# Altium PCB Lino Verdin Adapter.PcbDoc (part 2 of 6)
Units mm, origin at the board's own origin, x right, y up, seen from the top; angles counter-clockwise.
Board outline 69.6 x 35 mm, 8 copper layers (Top Layer, Mid 1, GND 1, Mid 2, Mid 3, GND 2, Mid 4, Bottom Layer), stack 1.198 mm thick; 208 components, 258 nets, 1063 pads, 1090 vias.
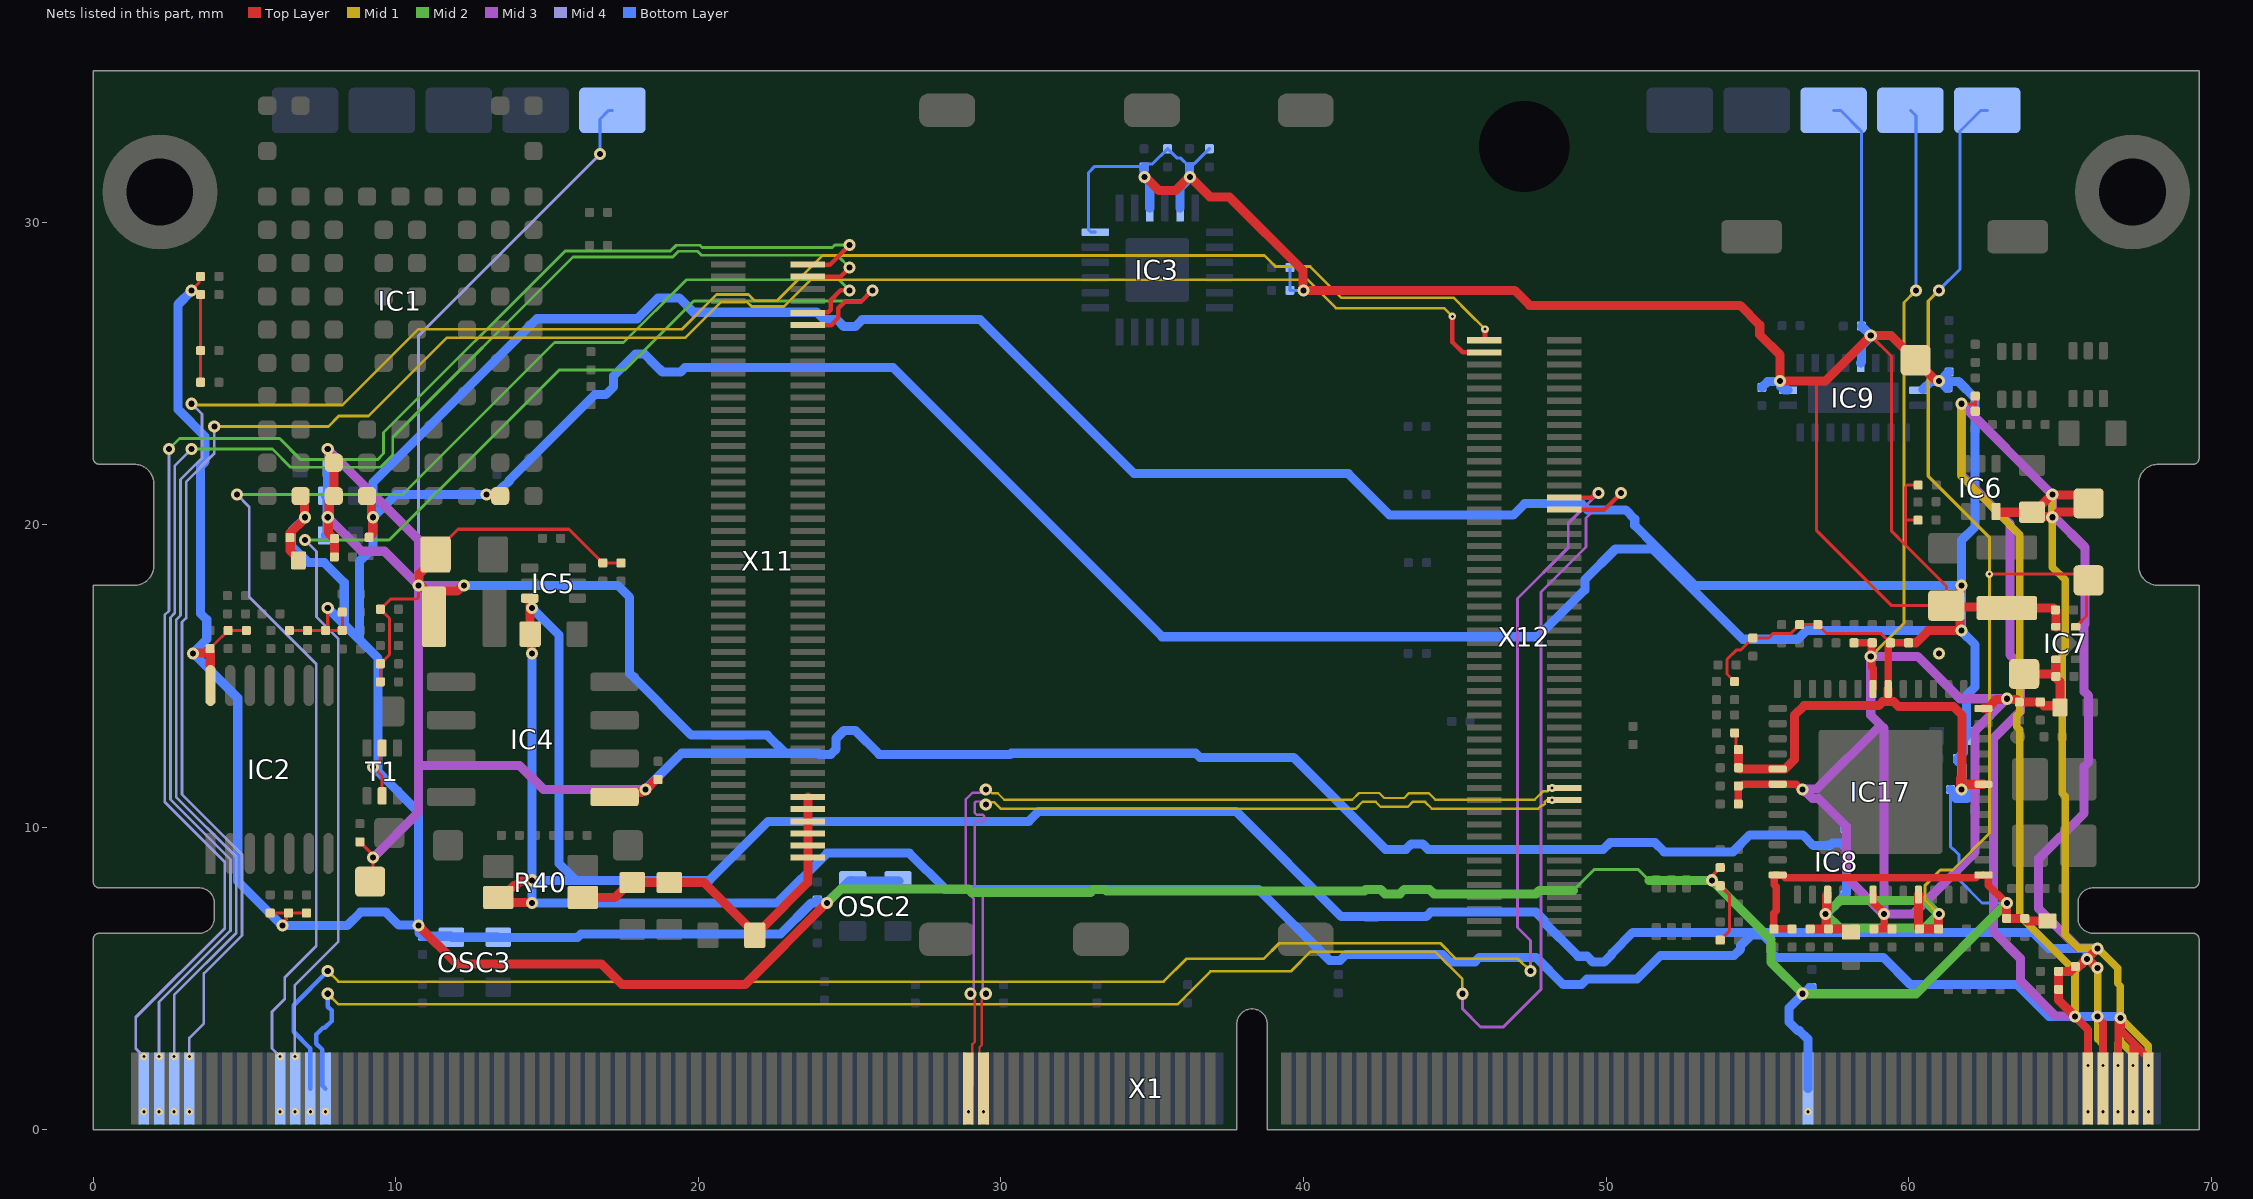
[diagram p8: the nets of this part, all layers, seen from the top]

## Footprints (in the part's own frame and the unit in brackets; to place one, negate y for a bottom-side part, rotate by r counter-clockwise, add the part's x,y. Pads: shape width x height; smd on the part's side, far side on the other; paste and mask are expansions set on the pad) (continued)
"QFN48P50_700X700X100L60X24T410X410 - SoM" [mm] "QFN, 48-Leads, Body 7.00x7.00mm, Pitch 0.50mm, Thermal Pad 4.1x4.1 mm, IPC High Density"
  rrect50% 0.6x0.24 smd: 1(-3.4,2.75) 2(-3.4,2.25) 3(-3.4,1.75) 4(-3.4,1.25) 5(-3.4,0.75) 6(-3.4,0.25) 7(-3.4,-0.25) 8(-3.4,-0.75) 9(-3.4,-1.25) 10(-3.4,-1.75) 11(-3.4,-2.25) 12(-3.4,-2.75) 25(3.4,-2.75) 26(3.4,-2.25) 27(3.4,-1.75) 28(3.4,-1.25) 29(3.4,-0.75) 30(3.4,-0.25) 31(3.4,0.25) 32(3.4,0.75) 33(3.4,1.25) 34(3.4,1.75) 35(3.4,2.25) 36(3.4,2.75)
  rrect50% 0.24x0.6 smd: 13(-2.75,-3.4) 14(-2.25,-3.4) 15(-1.75,-3.4) 16(-1.25,-3.4) 17(-0.75,-3.4) 18(-0.25,-3.4) 19(0.25,-3.4) 20(0.75,-3.4) 21(1.25,-3.4) 22(1.75,-3.4) 23(2.25,-3.4) 24(2.75,-3.4) 37(2.75,3.4) 38(2.25,3.4) 39(1.75,3.4) 40(1.25,3.4) 41(0.75,3.4) 42(0.25,3.4) 43(-0.25,3.4) 44(-0.75,3.4) 45(-1.25,3.4) 46(-1.75,3.4) 47(-2.25,3.4) 48(-2.75,3.4)
  rrect5% 4.1x4.1 smd paste-2539.97: 49(0,0)
  body extent -3.56,-3.56 3.56,3.56, height 0.9
RESC60X30X33L15L [mm] "0201 (0603 Metric), Chip SMD Resistor, High Density"
  rrect33% 0.3x0.3 smd: 1(-0.3,0) 2(0.3,0)
  body extent -0.3,-0.15 0.3,0.15, height 0.31
RESSC320X160X65L60N [mil] "1206 (3216 Metric) Chip SMD Resistor Side Concave, Normal Density"
  rrect15% 39.76x30 smd: 1(-55,20) 2(-55,-20) 3(55,-20) 4(55,20)
  body extent -63,-31 63,32, height 25
SODIMM_DDR4_no_Module [mm]
  rect 0.35x2.375 smd paste-127 mask-127: 1(-36.875,1.362) 3(-36.375,1.362) 5(-35.875,1.362) 7(-35.375,1.362) 9(-34.875,1.362) 11(-34.375,1.362) 13(-33.875,1.362) 15(-33.375,1.362) 17(-32.875,1.362) 19(-32.375,1.362) 21(-31.875,1.362) 23(-31.375,1.362) 25(-30.875,1.362) 27(-30.375,1.362) 29(-29.875,1.362) 31(-29.375,1.362) 33(-28.875,1.362) 35(-28.375,1.362) 37(-27.875,1.362) 39(-27.375,1.362) 41(-26.875,1.362) 43(-26.375,1.362) 45(-25.875,1.362) 47(-25.375,1.362) 49(-24.875,1.362) 51(-24.375,1.362) 53(-23.875,1.362) 55(-23.375,1.362) 57(-22.875,1.362) 59(-22.375,1.362) 61(-21.875,1.362) 63(-21.375,1.362) 65(-20.875,1.362) 67(-20.375,1.362) 69(-19.875,1.362) 71(-19.375,1.362) 73(-18.875,1.362) 75(-18.375,1.362) 77(-17.875,1.362) 79(-17.375,1.362) 81(-16.875,1.362) 83(-16.375,1.362) 85(-15.875,1.362) 87(-15.375,1.362) 89(-14.875,1.362) 91(-14.375,1.362) 93(-13.875,1.362) 95(-13.375,1.362) 97(-12.875,1.362) 99(-12.375,1.362) 101(-11.875,1.362) 103(-11.375,1.362) 105(-10.875,1.362) 107(-10.375,1.362) 109(-9.875,1.362) 111(-9.375,1.362) 113(-8.875,1.362) 115(-8.375,1.362) 117(-7.875,1.362) 119(-7.375,1.362) 121(-6.875,1.362) 123(-6.375,1.362) 125(-5.875,1.362) 127(-5.375,1.362) 129(-4.875,1.362) 131(-4.375,1.362) 133(-3.875,1.362) 135(-3.375,1.362) 137(-2.875,1.362) 139(-2.375,1.362) 141(-1.875,1.362) 143(-1.375,1.362) 145(1.125,1.362) 147(1.625,1.362) 149(2.125,1.362) 151(2.625,1.362) 153(3.125,1.362) 155(3.625,1.362) 157(4.125,1.362) 159(4.625,1.362) 161(5.125,1.362) 163(5.625,1.362) 165(6.125,1.362) 167(6.625,1.362) 169(7.125,1.362) 171(7.625,1.362) 173(8.125,1.362) 175(8.625,1.362) 177(9.125,1.362) 179(9.625,1.362) 181(10.125,1.362) 183(10.625,1.362) 185(11.125,1.362) 187(11.625,1.362) 189(12.125,1.362) 191(12.625,1.362) 193(13.125,1.362) 195(13.625,1.362) 197(14.125,1.362) 199(14.625,1.362) 201(15.125,1.362) 203(15.625,1.362) 205(16.125,1.362) 207(16.625,1.362) 209(17.125,1.362) 211(17.625,1.362) 213(18.125,1.362) 215(18.625,1.362) 217(19.125,1.362) 219(19.625,1.362) 221(20.125,1.362) 223(20.625,1.362) 225(21.125,1.362) 227(21.625,1.362) 229(22.125,1.362) 231(22.625,1.362) 233(23.125,1.362) 235(23.625,1.362) 237(24.125,1.362) 239(24.625,1.362) 241(25.125,1.362) 243(25.625,1.362) 245(26.125,1.362) 247(26.625,1.362) 249(27.125,1.362) 251(27.625,1.362) 253(28.125,1.362) 255(28.625,1.362) 257(29.125,1.362) 259(29.625,1.362)
  rect 0.35x2.375 smd far side paste-127 mask-127: 2(-36.625,1.362) 4(-36.125,1.362) 6(-35.625,1.362) 8(-35.125,1.362) 10(-34.625,1.362) 12(-34.125,1.362) 14(-33.625,1.362) 16(-33.125,1.362) 18(-32.625,1.362) 20(-32.125,1.362) 22(-31.625,1.362) 24(-31.125,1.362) 26(-30.625,1.362) 28(-30.125,1.362) 30(-29.625,1.362) 32(-29.125,1.362) 34(-28.625,1.362) 36(-28.125,1.362) 38(-27.625,1.362) 40(-27.125,1.362) 42(-26.625,1.362) 44(-26.125,1.362) 46(-25.625,1.362) 48(-25.125,1.362) 50(-24.625,1.362) 52(-24.125,1.362) 54(-23.625,1.362) 56(-23.125,1.362) 58(-22.625,1.362) 60(-22.125,1.362) 62(-21.625,1.362) 64(-21.125,1.362) 66(-20.625,1.362) 68(-20.125,1.362) 70(-19.625,1.362) 72(-19.125,1.362) 74(-18.625,1.362) 76(-18.125,1.362) 78(-17.625,1.362) 80(-17.125,1.362) 82(-16.625,1.362) 84(-16.125,1.362) 86(-15.625,1.362) 88(-15.125,1.362) 90(-14.625,1.362) 92(-14.125,1.362) 94(-13.625,1.362) 96(-13.125,1.362) 98(-12.625,1.362) 100(-12.125,1.362) 102(-11.625,1.362) 104(-11.125,1.362) 106(-10.625,1.362) 108(-10.125,1.362) 110(-9.625,1.362) 112(-9.125,1.362) 114(-8.625,1.362) 116(-8.125,1.362) 118(-7.625,1.362) 120(-7.125,1.362) 122(-6.625,1.362) 124(-6.125,1.362) 126(-5.625,1.362) 128(-5.125,1.362) 130(-4.625,1.362) 132(-4.125,1.362) 134(-3.625,1.362) 136(-3.125,1.362) 138(-2.625,1.362) 140(-2.125,1.362) 142(-1.625,1.362) 144(-1.125,1.362) 146(1.375,1.362) 148(1.875,1.362) 150(2.375,1.362) 152(2.875,1.362) 154(3.375,1.362) 156(3.875,1.362) 158(4.375,1.362) 160(4.875,1.362) 162(5.375,1.362) 164(5.875,1.362) 166(6.375,1.362) 168(6.875,1.362) 170(7.375,1.362) 172(7.875,1.362) 174(8.375,1.362) 176(8.875,1.362) 178(9.375,1.362) 180(9.875,1.362) 182(10.375,1.362) 184(10.875,1.362) 186(11.375,1.362) 188(11.875,1.362) 190(12.375,1.362) 192(12.875,1.362) 194(13.375,1.362) 196(13.875,1.362) 198(14.375,1.362) 200(14.875,1.362) 202(15.375,1.362) 204(15.875,1.362) 206(16.375,1.362) 208(16.875,1.362) 210(17.375,1.362) 212(17.875,1.362) 214(18.375,1.362) 216(18.875,1.362) 218(19.375,1.362) 220(19.875,1.362) 222(20.375,1.362) 224(20.875,1.362) 226(21.375,1.362) 228(21.875,1.362) 230(22.375,1.362) 232(22.875,1.362) 234(23.375,1.362) 236(23.875,1.362) 238(24.375,1.362) 240(24.875,1.362) 242(25.375,1.362) 244(25.875,1.362) 246(26.375,1.362) 248(26.875,1.362) 250(27.375,1.362) 252(27.875,1.362) 254(28.375,1.362) 256(28.875,1.362) 258(29.375,1.362) 260(29.875,1.362)
  silkscreen extent -37.18,2.9 -36.58,3.9
SOIC8P127_500X600X175L100X40_no_Silkscreen [mm] "SOIC-8, 8-Leads, Body 6.19mmx5.00mm, Pitch 1.27mm, IPC Medium Density"
  rrect30% 1.6x0.6 smd: 1(-2.7,1.905) 2(-2.7,0.635) 3(-2.7,-0.635) 4(-2.7,-1.905) 5(2.7,-1.905) 6(2.7,-0.635) 7(2.7,0.635) 8(2.7,1.905)
  body extent -3.11,-2.5 3.11,2.5, height 1.75
SOT563-6P50_160X60L30N [mm]
  rrect35% 0.57x0.3 smd: 1(-0.79,0.5) 2(-0.79,0) 3(-0.79,-0.5) 4(0.79,-0.5) 5(0.79,0) 6(0.79,0.5)
  silkscreen extent -0.99,-0.8 0,1.03, body extent -0.81,-0.8 0.81,0.8, height 0.58
T_Abracon_ASDMB-24.000MHZ-LC-T [mm]
  rrect20% 0.65x0.85 smd: 1(-0.825,-0.775) 2(0.825,-0.775) 3(0.825,0.775) 4(-0.825,0.775)
  silkscreen extent -1.49,-0.79 -1.46,-0.76, body extent -1.25,-1 1.25,1, height 0.86
TE-1551573-5 [mm]
  rrect50% 1.85x1.1 smd: 1(-0.425,0)
  body extent -2.85,-0.58 0.41,0.58, height 2.15
TESTPIN/2.20x1.50 [mm]
  rrect20% 1.5x2.2 smd paste-127 mask+0: 1(0,0)
TSSOP14P65_440X500X120L60X25 [mm] "TSSOP-14, 14-Leads, Body 4.5mmx5mm, Pitch 0.65mm, IPC High Density / TI: PW"
  rect 1.355x0.341 smd paste+0 mask+0.05: 1(-2.775,1.95)
  rrect100% 1.355x0.341 smd paste+0 mask+0.05: 2(-2.775,1.3) 3(-2.775,0.65) 4(-2.775,0) 5(-2.775,-0.65) 6(-2.775,-1.3) 7(-2.775,-1.95) 8(2.775,-1.95) 9(2.775,-1.3) 10(2.775,-0.65) 11(2.775,0) 12(2.775,0.65) 13(2.775,1.3) 14(2.775,1.95)
  silkscreen extent -1.6,-2.5 1.6,2.5, body extent -3.55,-2.6 3.55,2.6, height 0.25
UBLOX_MAYA-W1/W2 [mm]
  rrect50% 0.6x0.6 smd mask+0.05: A1(4.4,-6.6) A2(3.3,-6.6) A3(2.2,-6.6) A4(1.1,-6.6) A5(0,-6.6) A6(-1.1,-6.6) A7(-2.2,-6.6) A8(-3.3,-6.6) A9(-4.4,-6.6) B1(4.4,-5.5) B2(3.3,-5.5) B3(2.2,-5.5) B4(1.1,-5.5) B5(0,-5.5) B6(-1.1,-5.5) B7(-2.2,-5.5) B8(-3.3,-5.5) B9(-4.4,-5.5) C1(4.4,-4.4) C2(3.3,-4.4) C4(1.1,-4.4) C5(0,-4.4) C6(-1.1,-4.4) C8(-3.3,-4.4) C9(-4.4,-4.4) D1(4.4,-3.3) D2(3.3,-3.3) D3(2.2,-3.3) D7(-2.2,-3.3) D8(-3.3,-3.3) D9(-4.4,-3.3) E1(4.4,-2.2) E2(3.3,-2.2) E3(2.2,-2.2) E4(0.55,-2.2) E5(-0.55,-2.2) E7(-2.2,-2.2) E8(-3.3,-2.2) E9(-4.4,-2.2) F1(4.4,-1.1) F2(3.3,-1.1) F3(2.2,-1.1) F4(0.55,-1.1) F5(-0.55,-1.1) F7(-2.2,-1.1) F8(-3.3,-1.1) F9(-4.4,-1.1) G1(4.4,0) G2(3.3,0) G3(2.2,0) G4(0.55,0) G5(-0.55,0) G7(-2.2,0) G8(-3.3,0) G9(-4.4,0) H1(4.4,1.1) H2(3.3,1.1) H3(2.2,1.1) H4(0.55,1.1) H5(-0.55,1.1) H7(-2.2,1.1) H8(-3.3,1.1) H9(-4.4,1.1) J1(4.4,2.2) J2(3.3,2.2) J3(2.2,2.2) J4(0.55,2.2) J5(-0.55,2.2) J7(-2.2,2.2) J8(-3.3,2.2) J9(-4.4,2.2) K1(4.4,3.3) K2(3.3,3.3) K3(2.2,3.3) K4(1.1,3.3) K5(0,3.3) K6(-1.1,3.3) K7(-2.2,3.3) K8(-3.3,3.3) K9(-4.4,3.3) L1(4.4,4.8) L9(-4.4,4.8) M1(4.4,6.3) M2(3.3,6.3) M8(-3.3,6.3) M9(-4.4,6.3)
  Keep-Out Layer region: 5.2,6.7 2.9,6.7 2.9,5.9 4,5.9 4,3.7 -4,3.7 -4,5.9 -2.9,5.9 -2.9,6.7 -5.2,6.7 -5.2,6.95 5.2,6.95
  silkscreen extent -5.2,-7.35 5.85,6.95, body extent -5.2,-7.35 5.2,6.95, height 1.9
X2SON4P65_100X100X40L36X21T48X48-1x1mm [mm] "X2SON package 5-pin 1x1mm / SOT1226VV"
  rrect32% 0.25x0.31 smd paste-1 mask-0.31: 1(-0.535,0.325) 2(-0.535,-0.325) 3(0.535,-0.325) 4(0.535,0.325)
  rrect34% 0.58x0.58 smd rot 45 paste-0.065 mask-0.05: 5(0,0)
  Top Layer region: -0.66,-0.48 -0.2,-0.48 -0.2,-0.379 -0.409,-0.17 -0.66,-0.17
  Top Layer region: 0.66,0.48 0.2,0.48 0.2,0.379 0.409,0.17 0.66,0.17
  Top Layer region: 0.66,-0.48 0.2,-0.48 0.2,-0.379 0.409,-0.17 0.66,-0.17
  Top Layer region: -0.66,0.48 -0.2,0.48 -0.2,0.379 -0.409,0.17 -0.66,0.17
  body extent -0.5,-0.5 0.5,0.5, height 0.4

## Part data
C1 C6 C129 C135 C136 C147: library part CMP-00249-13, "Capacitor Ceramic X5R 10uF 6.3V 20% 0402", Case/Package=0402, Manufacturer Name=Generic, Max Operating Temperature=85°C, Min Operating Temperature=-55°C, Rating=6.3V, Tolerance=20%
C2 C3: library part CMP-00469-9, "Capacitor Ceramic X5R 2.2uF 16V 20% 0402", Case/Package=0402, Manufacturer Name=Generic, Max Operating Temperature=85°C, Min Operating Temperature=-55°C, Rating=16V, Tolerance=20%
C4 C5 C125 C126: library part CMP-00468-10, "Capacitor Ceramic X7R 10nF 10V 10% 0201", Case/Package=0201, Manufacturer Name=Generic, Max Operating Temperature=125°C, Min Operating Temperature=-55°C, Rating=10V, Tolerance=10%
C7 C8 C9 C30 C31 C32 C33 C127 C128 C134 C143 C144 C145 C146 C173 C174 C175 C176: library part CMP-00466-9, "Capacitor Ceramic X5R 1uF 6.3V 20% 0201", Case/Package=0201, Manufacturer Name=Generic, Max Operating Temperature=85°C, Min Operating Temperature=-55°C, Rating=6.3V, Tolerance=20%
C10 C11 C12: library part CMP-00477-9, "Capacitor Ceramic X5R 220nF 6.3V 20% 0201", Case/Package=0201, Manufacturer Name=Generic, Max Operating Temperature=85°C, Min Operating Temperature=-55°C, Rating=6.3V, Tolerance=20%
C13 C14: library part CMP-00458-9, "Capacitor Ceramic NP0 12pF 25V 5% 0201", Case/Package=0201, Manufacturer Name=Generic, Max Operating Temperature=125°C, Min Operating Temperature=-55°C, Rating=25V, Tolerance=5%
C15 C21 C28 C47 C48 C49 C50 C51 C130 C131 C132 C133 C137 C138 C139 C140 C141 C142 C148: library part CMP-00475-11, "Capacitor Ceramic X5R 100nF 6.3V 20% 0201", Case/Package=0201, Manufacturer Name=Generic, Max Operating Temperature=85°C, Min Operating Temperature=-55°C, Rating=6.3V, Tolerance=10%
C16 C17 C18 C19 C26 C35 C36 C37 C38 C39 C40 C41 C42 C43 C44 C45 C46: library part CMP-00463-10, "Capacitor Ceramic NP0 100pF 25V 5% 0201", Case/Package=0201, Manufacturer Name=Generic, Max Operating Temperature=125°C, Min Operating Temperature=-55°C, Rating=25V, Tolerance=5%
C20 C27: library part CMP-00470-9, "Capacitor Ceramic X5R 22uF 6.3V 20% 0805", Case/Package=0805, Manufacturer Name=Generic, Max Operating Temperature=85°C, Min Operating Temperature=-55°C, Rating=6.3V, Tolerance=20%
C22 C23 C24 C25 C29 C34: library part CMP-00250-13, "Capacitor Ceramic X5R 10uF 10V 20% 0603", Case/Package=0603, Manufacturer Name=Generic, Max Operating Temperature=85°C, Min Operating Temperature=-55°C, Rating=10V, Tolerance=20%
C124: library part CMP-00459-10, "Capacitor Ceramic NP0 22pF 25V 5% 0201", Case/Package=0201, Manufacturer Name=Generic, Max Operating Temperature=125°C, Min Operating Temperature=-55°C, Rating=25V, Tolerance=5%
FID1 FID2 FID3 FID4 FID5 FID6 FID7 FID8: library part CMP-00203-11, "Fiducial"
IC1: library part CMP-00751-13, "802.15.4, Bluetooth, WiFi 802.11a/b/g/n/ac/ax Transceiver Module 2.4GHz ~ 5GHz Antenna Not Included, U.FL Surface Mount", Case/Package=LGA-86, Frequency=5GHz, Manufacturer Name=U-Blox, Manufacturer Part No.=MAYA-W260-00B, Max Operating Temperature=85°C, Min Operating Temperature=-40°C
IC2: library part CMP-00864-2, "2-channel 1.65- to 5.5-V I2C/SMBus switch with interrupt, reset & voltage translation", Case/Package=TSSOP, Manufacturer Name=TI, Manufacturer Part No.=TCA9543APWR, Max Operating Temperature=85°C, Max Supply Voltage=5.5V, Min Operating Temperature=-40°C, Min Supply Voltage=1.65V, Nominal Supply Voltage=1.8V
IC3: library part CMP-00184-11, "Low-voltage translating 16-bit I2C-bus/SMBus I/O expander", Manufacturer Name=NXP, Manufacturer Part No.=PCAL6416AHF, Max Operating Temperature=85°C, Min Operating Temperature=-40°C
IC4: library part CMP-00192-8, "CURRENT/POWER MONITOR with I2C Interface", Manufacturer Name="Texas Instruments", Manufacturer Part No.=INA219BIDR, Max Operating Temperature=125°C, Min Operating Temperature=-40°C
IC5 IC6: library part CMP-00563-7, "Integrated Buck Regulator 2A", Case/Package=SOT563, Manufacturer Name="Texas Instruments", Manufacturer Part No.=TPS62A02DRLR, Max Operating Temperature=125°C, Min Operating Temperature=-40°C, Output Current=2A
IC7: library part CMP-00508-6, "LDO / Linear Voltage Regulator (Vout=1.0V, Iout=500mA(max), Vin(max)=5.5V), X2SON, -40C to +85C", Case/Package=X2SON, Manufacturer Name="Texas Instruments", Manufacturer Part No.=TLV75510PDQNR, Max Operating Temperature=85°C, Min Operating Temperature=-40°C
IC8: library part CMP-00571-5, "LDO / Linear Voltage Regulator (Vout=2.5V, Iout=500mA(max), Vin(max)=5.5V), X2SON, -40C to +85C", Case/Package=X2SON4, Manufacturer Name="Texas Instruments", Manufacturer Part No.=TLV75525PDQNR, Max Operating Temperature=85°C, Min Operating Temperature=-40°C
IC9: library part CMP-00398-8, "Differential Multiplexer, 2 Channel, 20-VQFN", Case/Package="20-VFQFN Exposed Pad", Manufacturer Name="Texas Instruments", Manufacturer Part No.=TMUXHS4212IRKS, Max Operating Temperature=105°C, Min Operating Temperature=-40°C
IC17: library part CMP-00505-11, "Gigabit Ethernet Transceiver with RGMII (DP83867, QFN-48 (7mmx7mm) Leadless, -40C to +85C", Case/Package=HVQCCN, Manufacturer Name="Texas Instruments", Manufacturer Part No.=DP83867IRRGZR, Max Operating Temperature=85°C, Min Operating Temperature=-40°C, Temperature Range="-40C to +85C"
L1 L2: library part CMP-00421-8, "Inductor 1uH, 20%, Irms=1.85A, DCR= 60mOhm, 1008 (2520 metric)", DC Resistance=60m, Manufacturer Name="Taiyo Yuden", Manufacturer Part No.=MBMK2520T1R0M, Max Operating Temperature=125°C, Min Operating Temperature=-40°C, Package="1008 (2520 metric)", Rating=1.85A, Temperature Range="-40C to +125C", Tolerance=20%
MECH1: library part CMP-00975-3, "Round Standoff M2x0.4 (1.50mm height)", Manufacturer Name=Wurth, Manufacturer Part No.=9774015243R
OSC1: library part CMP-00208-13, "25MHz Crystal, 3.2x2.5mm, 20ppm, 10pF, 40 Ohm, -40C to +85C", Frequency=25MHz, Frequency Stability=20, Load Capacitance=10pF, Manufacturer Name=Qantek, Manufacturer Part No.=QC3225.0000H47R3, Max Operating Temperature=85°C, Min Operating Temperature=-40°C, Package="3.2mm X 2.5mm"
OSC2: library part CMP-00761-5, "25MHz Low Power LVCMOS output BAW Oscillator", Frequency=25MHz, Manufacturer Name="Texas Instruments", Manufacturer Part No.=CDC6CE025000ADLFR, Max Operating Temperature=105°C, Min Operating Temperature=-40°C
OSC3: library part CMP-00985-1, "24.576MHz Oscillator, 2.5x2.0mm, 50ppm, 1.8V-3.3V, -40C to +85C", Frequency=24.576MHz, Frequency Stability=50, Manufacturer Name=Epson, Manufacturer Part No.="SG-210STF 24.5760ML0", Max Operating Temperature=85°C, Min Operating Temperature=-40°C, Package="2.5mm x 2.0mm", Tolerance=50ppm
Q3 T1 T2 T3: library part CMP-00121-16, "Dual N-Channel 20V (D-S)  MOSFET, 20 V, 540 mA, SOT−563", Drain Current-Max (ID)=540mA, Drain-source On Resistance-Max=0.55, DS Breakdown Voltage-Min=20V, Manufacturer Name=onsemi, Manufacturer Part No.=NTZD3154NT1G, Max Operating Temperature=150°C, Min Operating Temperature=-55°C
R1 R2 R9 R10 R19 R20 R25 R28 R31 R32 R33 R34 R35 R53: library part CMP-00402-19, "Resistor 0 ohm 50mW 5% 0201", Case/Package=0201, Manufacturer Name=Generic, Max Operating Temperature=125°C, Min Operating Temperature=-55°C, Rating=50mW, Tolerance=5%
R3 R4 R5 R6 R7 R8 R13 R14 R21 R39 R42 R50: library part CMP-00436-14, "Resistor 100K ohm 50mW 1% 0201", Case/Package=0201, Manufacturer Name=Generic, Max Operating Temperature=155°C, Min Operating Temperature=-55°C, Rating=50mW, Tolerance=1%
R11 R12 R16 R17 R26 R27 R29 R30 R46: library part CMP-00441-14, "Resistor 2.2K ohm 50mW 5% 0201", Case/Package=0201, Manufacturer Name=Generic, Max Operating Temperature=155°C, Min Operating Temperature=-55°C, Rating=50mW, Tolerance=5%
R15 R18 R22 R24 R48 R49 R83 R90: library part CMP-00426-16, "Resistor 10K ohm 50mW 1% 0201", Case/Package=0201, Manufacturer Name=Generic, Max Operating Temperature=155°C, Min Operating Temperature=-55°C, Rating=50mW, Tolerance=1%
R36 R37: library part CMP-00428-14, "Resistor 10 ohm 50mW 5% 0201", Case/Package=0201, Manufacturer Name=Generic, Max Operating Temperature=155°C, Min Operating Temperature=-55°C, Rating=50mW, Tolerance=5%
R38: library part CMP-00445-14, "Resistor 453K ohm 50mW 1% 0201", Case/Package=0201, Manufacturer Name=Generic, Max Operating Temperature=155°C, Min Operating Temperature=-55°C, Rating=50mW, Tolerance=1%
R40: library part CMP-00325-8, "10 mOhms ±1% 0.5W,Chip Resistor 1206 (3216 Metric) Current Sense, Moisture Resistant, Pulse Withstanding Metal Element", Case/Package=1206, Manufacturer Name=Vishay, Manufacturer Part No.=WSK1206R0100FEA18, Max Operating Temperature=170°C, Min Operating Temperature=-65°C, Rating=500mW, Tolerance=1%
R41: library part CMP-00827-2, "Resistor 200K ohm 50mW 1% 0201", Case/Package=0201, Manufacturer Name=Generic, Max Operating Temperature=155°C, Min Operating Temperature=-55°C, Rating=50mW, Tolerance=1%
R43 R44 R45 R47: library part CMP-00425-14, "Resistor 1M ohm 50mW 5% 0201", Case/Package=0201, Manufacturer Name=Generic, Max Operating Temperature=155°C, Min Operating Temperature=-55°C, Rating=50mW, Tolerance=5%
R51 R52: library part CMP-00430-14, "Resistor 22 ohm 50mW 5% 0201", Case/Package=0201, Manufacturer Name=Generic, Max Operating Temperature=155°C, Min Operating Temperature=-55°C, Rating=50mW, Tolerance=5%
R82: library part CMP-00424-15, "Resistor 1K ohm 50mW 5% 0201", Case/Package=0201, Manufacturer Name=Generic, Max Operating Temperature=155°C, Min Operating Temperature=-55°C, Rating=50mW, Tolerance=5%
R84 R85 R89 R91 R93 R94: library part CMP-00456-14, "Resistor 5.76K ohm 50mW 1% 0201", Case/Package=0201, Manufacturer Name=Generic, Max Operating Temperature=155°C, Min Operating Temperature=-55°C, Rating=50mW, Tolerance=1%
R86 R87 R88 R95 R96 R97 R98 R123: library part CMP-00452-14, "Resistor 2.49K ohm 50mW 1% 0201", Case/Package=0201, Manufacturer Name=Generic, Max Operating Temperature=155°C, Min Operating Temperature=-55°C, Rating=50mW, Tolerance=1%
R124: library part CMP-00429-14, "Resistor 11K ohm 50mW 1% 0201", Case/Package=0201, Manufacturer Name=Generic, Max Operating Temperature=155°C, Min Operating Temperature=-55°C, Rating=50mW, Tolerance=1%
SW1: library part CMP-00979-2, "DIP Switch SPST 1x Surface Mount", Manufacturer Name=CON-TE-Connectivity, Manufacturer Part No.=EDS01SGRSTR04Q, Max Operating Temperature=85°C, Max Voltage Rating (DC)=24V, Min Operating Temperature=-20°C, Rating=25mA
TP1 TP2 TP3 TP4 TP5 TP6 TP7 TP8 TP9 TP10: library part CMP-00568-6, "Testpin 1.5x2.2mm", Manufacturer Name=Generic
TP11: library part CMP-00566-8, "Testpin Round 0.5mm", Manufacturer Name=Generic
TP12 TP13 TP14 TP15 TP16 TP17 TP18 TP19 TP20: library part CMP-00567-9, "Testpin Square 1.0mm", Manufacturer Name=Generic
X1: library part CMP-00731-8, "DDR4 SODIMM Card Edge, 260 pins, 0.5mm Pitch", Manufacturer Name=Generic, Manufacturer Part No.="No Physical Component"
X11: library part CMP-00961-5, "LINO Primary Connector Carrier", Manufacturer Name=Amphenol, Manufacturer Part No.=10164227-1001A1RLF
X12: library part CMP-00962-5, "LINO Secondary Connector", Manufacturer Name=Amphenol, Manufacturer Part No.=10164227-1001A1RLF
X21 X23 X26 X27 X29 X32: library part CMP-00967-1, "Single C-Clip Spring Contact, 1.9 mm High, 1.3mm Low, 2.15 mm Uncompressed Height, 3.26 mm Length", Manufacturer Name=TE-Connectivity, Manufacturer Part No.=1551573-5, Max Operating Temperature=85°C, Min Operating Temperature=-40°C

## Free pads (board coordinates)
  round 3.8 hole 2.2: 2(2.2,31) 2(67.4,31)

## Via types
v1: diameter 0.4, hole 0.2, Top Layer to Bottom Layer, tented both sides, 600 vias
v2: diameter 0.25, hole 0.1, Mid 4 to Bottom Layer, tented both sides, 229 vias
v3: diameter 0.25, hole 0.1, Top Layer to Mid 1, tented both sides, 216 vias
v4: diameter 0.25, hole 0.1, Top Layer to Mid 1, tented top, 41 vias
v5: diameter 0.4, hole 0.2, Top Layer to Bottom Layer, 4 vias

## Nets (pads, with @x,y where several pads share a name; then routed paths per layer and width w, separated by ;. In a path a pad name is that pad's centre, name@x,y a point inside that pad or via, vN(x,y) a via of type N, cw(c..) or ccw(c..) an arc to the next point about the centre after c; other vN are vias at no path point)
+V1.0_ETH: C30.2 C137.2 C138.2 C139.2 C147.2 C148.2 C173.2 C174.2 C175.2 C176.2 IC7.1 IC17.6 IC17.24 IC17.31 IC17.42 TP9.1 TP19.1 | length 63.7
  Top Layer w0.25: C175.2@54.375,10.77 C137.2@54.375,11.37 54.4,11.395 54.494,11.395 54.519,11.42 IC17.42@55.67,11.42 ; 55.095,11.42 56.289,11.42 56.459,11.25 v1(56.5,11.25) ; C173.2@58.2,16.1 C139.2@58.8,16.1 58.775,16.075 58.775,15.719 58.765,15.709 58.75,15.709 58.779,15.681 58.779,15.296 58.825,15.25 IC17.31@58.825,14.575 ; IC17.6@58.825,7.775 58.83,7.77 58.83,7.531 59.19,7.171 v1(59.19,7.13) 59.19,6.662 59.21,6.642 ; C138.2@58.85,6.642 59.21,6.642 ; C174.2@59.45,6.642 59.21,6.642
  Top Layer w0.3: IC17.24@62.475,13.925 62.595,13.925 62.901,14.231 63.231,14.231 v1(63.25,14.25) 63.269,14.231 63.577,14.231 C148.2@63.663,14.145 64.263,14.145 C176.2@64.291,14.117 ; TP19.1@63.819,15.07 64.785,15.07 C30.2@64.865,14.989 ; C176.2@64.353,14.145 64.478,14.02 64.949,14.02 C147.2@65.003,13.967 65.003,14.813 64.865,14.951 C30.2@64.865,14.989 ; IC7.1@64.87,15.554 64.865,15.549 C30.2@64.865,14.989
  Mid 3 w0.3: 59.078,13.378 56.969,11.269 56.519,11.269 v1(56.5,11.25) 56.527,11.25 56.827,10.95 57.026,10.95 57.95,10.026 57.95,8.343 59.163,7.13 v1(59.19,7.13) ; 59.078,13.378 59.19,13.266 v1(59.19,7.13) ; 59.078,13.378 58.75,13.706 v1(58.75,15.65) 60.3,15.65 61.7,14.25 v1(63.25,14.25) 62.2,13.2 62.2,9.184 60.146,7.13 v1(59.19,7.13)
  Mid 1 w0.1: v1(58.75,15.65) 59.85,16.75 59.85,27.35 v1(60.25,27.75)
  Bottom Layer w0.1: TP9.1@60.06,33.7 60.25,33.51 v1(60.25,27.75)
+V1.8: C6.2 C7.2 C8.2 C9.2 C10.2 C11.2 C12.2 C26.2 C27.2 C28.2 C31.2 C47.2 C48.2 C49.2 C50.2 C51.2 C132.2 C133.2 C134.2 C135.2 C136.2 C140.2 C141.2 C142.2 C143.2 C144.2 C145.2 C146.2 IC1.A2 IC1.A6 IC1.A8 IC2.14 IC3.18 IC3.21 IC3.23 IC7.4 IC9.1 IC9.6 IC9.10 IC17.13 IC17.19 IC17.30 IC17.41 IC17.48 L2.2 OSC2.1 OSC2.4 OSC3.1 OSC3.4 R3.1 R4.1 R5.1 R6.1 R11.2 R12.2 R13.1 R14.1 R15.2 R16.2 R17.2 R18.2 R21.1 R22.2 R24.2 R26.2 R29.2 R41.2 R48.2 R50.2 R82.2 R83.2 R84.2 R85.2 R89.2 R90.2 R91.2 R93.2 R94.2 T1.2 T1.5 TP8.1 TP18.1 X1.214 | length 415.6
  Top Layer w0.1: R6.1@3.55,24.71 R5.1@3.55,25.76 R3.1@3.55,27.61 3.467,27.693 3.307,27.693 v1(3.25,27.75) 3.489,27.989 3.489,28.149 R4.1@3.55,28.21 ; C10.2@3.86,15.908 3.96,16.008 R11.2@4.46,16.508 R12.2@5.06,16.508 ; R15.2@5.85,7.17 6.22,7.17 R13.1@6.45,7.17 ; v1@6.256,6.75 6.256,6.836 6.378,6.959 6.378,7.098 R13.1@6.45,7.17 ; R17.2@6.48,16.508 6.482,16.51 R18.2@7.682,16.51 ; R14.1@7.05,7.17 R13.1@6.45,7.17 ; R18.2@7.68,16.508 R18.2@7.682,16.51 ; v1(7.75,17.25) 7.75,16.578 R18.2@7.682,16.51 ; R26.2@8.23,17.112 R29.2@8.23,16.512 8.228,16.51 R18.2@7.682,16.51 ; T1.5@9.55,11.043 9.55,11.7 v1(9.25,12) 9.497,12.247 9.497,12.57 T1.2@9.55,12.623 ; R89.2@53.775,6.27 54.075,6.57 54.075,7.77 R90.2@53.775,8.07 53.652,8.193 53.639,8.193 53.5,8.331 53.5,8.345 53.514,8.345 53.557,8.389 53.557,8.453 R91.2@53.775,8.67 ; R93.2@54.25,14.82 54,15.07 54,15.553 54.303,15.857 54.447,15.857 R85.2@54.85,16.26 55.375,16.26 55.515,16.4 56.1,16.4 R84.2@56.4,16.7 R83.2@57,16.7 57.3,16.4 59.1,16.4 C141.2@59.4,16.1 ; R94.2@54.3,13.07 54.3,12.645 C144.2@54.375,12.57 ; 56.95,24.75 56.95,19.82 59.443,17.327 C27.2@61.25,17.327 61.25,17.973 59.9,19.323 ; v1(58.75,26.25) 59.44,25.56 59.44,19.783 59.9,19.323 ; TP18.1@60.23,25.44 TP18.1@60.316,25.354 ; R41.2@60.306,20.152 59.9,20.151 ; C26.2@60.316,21.313 59.959,21.313 59.9,21.254 59.9,20.151 ; 59.9,19.323 59.9,20.151
  Top Layer w0.25: C143.2@56.15,6.642 C133.2@55.55,6.642 55.55,7.166 55.625,7.241 55.625,8.04 55.56,8.105 55.56,8.42 55.565,8.425 IC17.48@55.675,8.425 55.68,8.42 55.85,8.42 55.93,8.34 62.22,8.34 62.3,8.42 62.47,8.42 IC17.13@62.475,8.425 ; IC17.30@59.325,14.575 59.325,16.025 C141.2@59.4,16.1 C146.2@60,16.1 ; IC17.13@62.631,8.42 62.631,8.089 63.22,7.5 v1(63.25,7.5)
  Top Layer w0.3: v1(3.3,15.75) 3.319,15.769 3.721,15.769 C10.2@3.86,15.908 3.86,15.821 3.867,15.814 3.867,14.695 IC2.14@3.875,14.687 ; C6.2@6.781,18.825 6.781,18.875 6.51,19.146 6.51,19.733 7,20.223 v1(7,20.25) 6.981,20.269 6.981,20.819 IC1.A8@6.85,20.95 ; IC1.A6@9.05,20.95 9.2,20.8 9.2,20.327 9.25,20.277 v1(9.25,20.25) 9.231,20.231 9.231,19.698 C8.2@9.12,19.587 ; v1(10.75,6.75) 12.01,5.49 16.79,5.49 17.48,4.8 21.54,4.8 v1@24.25,7.51 ; v1(13,21) 13.019,20.981 13.419,20.981 IC1.A2@13.45,20.95 ; v1(34.75,31.5) 34.769,31.5 35.219,31.05 35.781,31.05 36.231,31.5 v1(36.25,31.5) 36.916,30.834 37.553,30.834 39.986,28.4 39.986,27.764 v1(40,27.75) 46.979,27.75 47.479,27.25 54.43,27.25 55.08,26.6 55.08,26.283 55.75,25.614 v1(55.75,24.75) 56.95,24.75 57.25,24.75 v1(58.75,26.25) 59.42,26.25 TP18.1@60.23,25.44 ; C144.2@54.375,12.57 C140.2@54.375,11.97 54.42,11.925 IC17.41@55.675,11.925 55.913,11.925 56.225,12.237 56.225,12.613 56.225,13.705 56.545,14.025 59.013,14.025 59.144,14.156 59.325,14.156 ; IC17.30@59.325,14.575 59.325,14.156 ; C146.2@60,16.1 60.25,16.1 60.65,16.5 v1(61.75,16.5) 61.75,16.527 61.7,16.577 61.7,16.977 C27.2@61.389,17.288 ; TP18.1@60.316,25.354 60.901,24.769 60.981,24.769 v1(61,24.75) ; C27.2@61.25,17.327 C27.2@61.35,17.327 ; v1@61.712,11.222 v1@61.731,11.241 ; v1@61.744,11.254 v1@61.731,11.241 ; v1(61.75,11.25) 61.777,11.25 61.952,11.425 IC17.19@62.475,11.425 ; v1(61.75,18) 61.75,17.973 61.7,17.923 61.7,17.677 C27.2@61.35,17.327 ; v1(63.25,7.5) 63.24,7.49 C132.2@63.24,6.99 C134.2@63.84,6.99 63.928,6.902 C135.2@64.59,6.902 ; IC7.4@64.87,16.624 64.87,17.173 C31.2@64.854,17.189 64.794,17.249 L2.2@63.25,17.249 63.211,17.288 C27.2@61.389,17.288 ; 59.325,14.156 59.506,14.156 59.662,14 61.479,14 61.77,13.709 61.77,11.674 61.72,11.624 61.72,11.307 61.731,11.296 v1@61.731,11.241 ; C27.2@61.35,17.327 C27.2@61.389,17.288
  Mid 2 w0.1: 48.92,7.915 49.605,8.6 51.07,8.6 51.42,8.25
  Mid 2 w0.3: v1(24.25,7.5) 24.71,7.96 28.926,7.96 29.031,7.855 32.969,7.855 33.064,7.95 33.436,7.95 33.486,7.9 42.014,7.9 42.059,7.945 42.55,7.945 42.695,7.8 43.186,7.8 43.336,7.95 44.164,7.95 44.314,7.8 47.686,7.8 47.801,7.915 48.92,7.915 ; 51.42,8.25 51.77,8.25 v1(53.5,8.25) 55.45,6.3 55.45,5.55 v1(56.5,4.5) 60.25,4.5 v1(63.25,7.5)
  Bottom Layer w0.1: IC3.18@33.12,29.672 32.975,29.672 32.9,29.747 32.9,31.645 33.105,31.85 34.715,31.85 C11.2@34.735,31.83 ; v1@34.735,31.515 v1@34.742,31.508 ; v1(34.75,31.5) v1@34.742,31.508 ; R50.2@36.89,32.43 36.39,31.93 36.33,31.93 C12.2@36.23,31.83 35.93,32.13 35.81,32.13 R22.2@35.51,32.43 35.01,31.93 34.835,31.93 C11.2@34.735,31.83 ; R21.1@39.55,28.5 R24.2@39.55,27.75 v1(40,27.75) ; TP8.1@57.52,33.7 57.748,33.7 58.44,33.008 C49.2@58.44,26.57 ; C142.2@61.39,11.25 61.39,9.349 61.449,9.29 61.465,9.29 61.67,9.085 61.67,8.26 62.43,7.5 v1(63.25,7.5) ; C11.2@34.735,31.83 34.75,31.815 34.742,31.807 v1@34.742,31.508
  Bottom Layer w0.3: v1(3.25,27.75) 3.25,27.731 2.8,27.281 2.8,23.814 3.7,22.914 3.7,22.086 3.55,21.936 3.55,17.064 3.75,16.864 3.75,16.219 3.3,15.769 v1(3.3,15.75) 4.775,14.275 4.775,8.225 v1(6.25,6.75) 8.386,6.75 8.836,7.2 9.668,7.2 10.1,6.768 10.732,6.768 v1(10.75,6.75) ; v1(7,20.25) 7,20.231 6.55,19.781 6.55,19.314 7.114,18.75 7.636,18.75 8.295,18.091 8.295,16.705 ; v1(7.75,17.25) 8.295,16.705 ; v1(9.25,12) 9.415,11.835 ; C50.2@23.93,7.5 23.74,7.5 22.72,6.48 16.124,6.48 16.002,6.358 13.37,6.358 13.36,6.368 11.86,6.368 11.828,6.4 C51.2@10.885,6.4 10.769,6.516 10.769,6.731 v1(10.75,6.75) ; C50.2@23.93,7.6 24.011,7.519 24.231,7.519 v1(24.25,7.5) 24.975,8.225 OSC2.4@25.075,8.225 ; OSC2.4@25.062,8.237 OSC2.4@25.075,8.225 ; OSC2.1@26.625,8.225 OSC2.1@26.6,8.225 OSC2.4@25.1,8.225 OSC2.4@25.075,8.225 ; v1@34.735,31.515 C11.2@34.735,31.83 ; v1(34.75,31.5) 34.75,31.473 34.92,31.303 IC3.21@34.92,30.472 ; IC3.23@35.92,30.472 35.92,31.143 36.25,31.473 v1(36.25,31.5) 36.231,31.519 C12.2@36.23,31.83 ; C47.2@55.15,24.54 55.341,24.731 55.731,24.731 v1(55.75,24.75) 55.769,24.731 55.769,24.576 55.895,24.45 IC9.1@56.02,24.45 ; X1.214@56.675,1.362 56.675,3 56.393,3.282 56.332,3.282 56.05,3.564 56.05,4.031 56.5,4.481 v1(56.5,4.5) 56.527,4.5 56.727,4.7 C28.2@56.8,4.7 ; IC9.6@58.42,25.35 58.445,25.375 58.445,25.918 58.75,26.223 v1(58.75,26.25) 58.75,26.26 C49.2@58.44,26.57 ; IC9.10@60.47,24.475 60.726,24.731 60.981,24.731 v1(61,24.75) 61.014,24.736 v1@61.041,24.736 ; C48.2@61.3,24.53 61.247,24.53 v1@61.041,24.736 ; R48.2@61.34,25.05 61.327,25.05 61.027,24.75 v1@61.041,24.736 ; C142.2@61.39,11.25 61.46,11.18 v1@61.75,11.18 ; 61.564,10.951 61.936,10.951 61.965,10.98 61.99,10.98 R82.2@62.19,11.18 62.139,11.231 61.769,11.231 v1(61.75,11.25) 61.75,11.277 61.77,11.297 61.77,12.046 61.61,12.206 C145.2@61.61,12.27 61.82,12.48 61.82,12.92 C136.2@61.92,13.02 61.92,14.363 62.2,14.643 62.2,16.031 61.75,16.481 v1(61.75,16.5) ; 8.295,16.705 8.8,16.2 ; 8.8,16.2 9.415,15.585 9.415,11.835 ; 8.8,16.2 8.8,18.793 9.25,19.243 v1(9.25,20.25) ; v1(9.25,20.25) 9.25,21.4 14.66,26.81 17.98,26.81 18.67,27.5 19.364,27.5 19.839,27.025 23.914,27.025 24.159,26.78 24.584,26.78 24.814,26.55 25.186,26.55 25.416,26.78 29.31,26.78 34.4,21.69 41.48,21.69 42.85,20.32 46.934,20.32 47.314,20.7 49.18,20.7 49.39,20.49 50.646,20.49 50.95,20.186 50.95,19.98 51.635,19.295 52.93,18 v1(61.75,18) ; v1(9.25,20.25) 10,21 v1(13,21) 13.019,21.019 13.299,21.019 C9.2@13.35,21.07 13.55,21.27 13.575,21.27 13.75,21.445 13.75,21.47 16.58,24.3 16.936,24.3 17.2,24.564 17.2,24.92 17.93,25.65 18.214,25.65 18.584,25.28 18.814,25.05 19.414,25.05 19.564,25.2 26.43,25.2 35.33,16.3 47.75,16.3 49.3,17.85 49.3,18.186 50.314,19.2 51.54,19.2 52.835,17.905 54.524,16.216 56.335,16.216 56.618,16.5 v1(61.75,16.5) ; 9.415,11.835 10.75,10.5 v1(10.75,6.75) ; v1@61.041,24.736 61.65,24.736 62.2,24.186 62.2,19.94 61.75,19.49 v1(61.75,18) ; v1(61.75,16.5) v1(61.75,18)
  other v1: 61,15.75
  other v2: 56.675,0.6
+V2.5_ETH: C32.2 C127.2 C128.2 C129.2 C130.2 C131.2 IC7.3 IC8.1 IC17.3 IC17.9 TP10.1 TP20.1 | length 49.3
  Top Layer w0.1: v4(62.67,18.37) 65.745,18.37 TP20.1@65.951,18.164 65.884,18.097 65.884,16.988 65.625,16.729 65.625,16.699 65.55,16.624 IC7.3@65.52,16.624
  Top Layer w0.3: C128.2@56.75,6.642 C130.2@57.35,6.642 ; IC17.3@57.325,7.775 57.295,7.745 57.295,7.202 57.25,7.157 v1(57.25,7.13) 57.269,7.111 57.269,6.722 C130.2@57.35,6.642 ; C129.2@58.1,6.542 58,6.642 C130.2@57.35,6.642 ; IC17.9@60.325,7.775 60.325,6.677 C131.2@60.36,6.642 C127.2@60.99,6.642 60.99,7.12 v1(61,7.13)
  Mid 2 w0.3: v1(57.25,7.13) v1@57.269,7.13 ; v1(61,7.13) v1@60.981,7.13 ; v1@57.269,7.13 57.719,6.68 60.531,6.68 v1@60.981,7.13 ; v1@57.269,7.13 57.719,7.58 60.531,7.58 v1@60.981,7.13
  Mid 1 w0.1: v1(61,7.13) 60.55,7.58 60.55,8.089 61.051,8.59 61.465,8.59 62.67,9.795 v4(62.67,18.37) 62.67,19.585 60.65,21.605 60.65,27.4 v1(61,27.75)
  Bottom Layer w0.1: v1(61,27.75) 61.7,28.45 61.7,33.008 62.392,33.7 TP10.1@62.6,33.7
  Bottom Layer w0.3: v1(57.25,7.13) 57.277,7.13 57.508,7.361 57.521,7.361 57.697,7.536 57.697,7.561 C32.2@57.897,7.761 57.945,7.809 57.945,8.321 IC8.1@57.95,8.326
+V3.3: C1.2 C2.2 C3.2 C4.2 C5.2 C19.2 C20.2 C21.2 C33.1 IC1.A7 IC1.B7 IC4.5 IC8.3 IC8.4 L1.2 R27.2 R30.2 R32.2 R34.2 R38.2 TP5.1 TP15.1 | length 132
  Top Layer w0.1: R27.2@8.812,9.521 9.193,9.14 9.193,9.057 v1(9.25,9) 9.25,8.308 TP15.1@9.15,8.208 ; R30.2@9.489,14.808 R32.2@9.489,15.408 9.789,15.708 9.789,16.908 R34.2@9.489,17.208 9.747,17.467 9.749,17.467 9.833,17.55 10.691,17.55 10.75,17.609 v1(10.75,18) ; C20.2@11.316,19.018 11.316,19.116 12.053,19.853 15.726,19.853 R38.2@16.841,18.738 C19.2@17.441,18.738
  Top Layer w0.3: v1(7.75,22.5) 7.75,22.473 7.8,22.423 7.8,22.2 IC1.B7@7.95,22.05 IC1.A7@7.95,20.95 7.8,20.8 7.8,20.327 7.75,20.277 v1(7.75,20.25) 7.769,20.231 7.769,19.741 C5.2@7.97,19.54 C4.2@7.97,18.94 ; L1.2@11.266,16.955 L1.2@11.266,17.555 ; C20.2@11.316,19.018 11.316,18.918 10.769,18.371 10.769,18.019 v1(10.75,18) 10.777,18 10.809,17.968 10.853,17.968 L1.2@11.266,17.555 ; v1(12.25,18) 12.223,18 12.028,17.805 11.516,17.805 L1.2@11.266,17.555 ; IC4.5@17.23,11.002 17.38,11.152 18.125,11.152 18.223,11.25 v1(18.25,11.25) 18.277,11.25 18.61,11.583 C21.2@18.666,11.583
  Mid 3 w0.3: v1(7.75,20.25) 8.875,19.125 9.625,19.125 v1(10.75,18) ; v1(7.75,22.5) 10.75,19.5 v1(10.75,18) ; v1(9.25,9) 10.75,10.5 10.75,12.05 ; v1(12.25,18) v1(10.75,18) ; v1(18.25,11.25) 14.886,11.25 14.086,12.05 10.75,12.05 ; 10.75,12.05 v1(10.75,18)
  Mid 4 w0.1: v1(10.75,18) 10.75,26.25 v1(16.75,32.25)
  Bottom Layer w0.1: v1(16.75,32.25) 16.75,33.408 17.042,33.7 TP5.1@17.16,33.7
  Bottom Layer w0.3: C2.2@7.67,19.65 7.731,19.711 7.731,20.231 v1(7.75,20.25) 7.731,20.269 7.731,20.899 C3.2@7.67,20.96 7.751,21.041 7.751,21.779 C1.2@7.832,21.86 7.769,21.923 7.769,22.481 v1(7.75,22.5) ; v1(10.75,18) v1(12.25,18) 17.33,18 17.73,17.6 17.73,15.09 19.77,13.05 22.28,13.05 22.88,12.45 ; v1(18.25,11.25) 19.31,12.31 19.45,12.45 22.88,12.45 ; C33.1@57.892,9.961 57.95,9.903 IC8.4@57.95,9.416 ; IC8.4@57.95,9.396 IC8.4@57.95,9.416 ; 22.88,12.45 23.958,12.45 23.998,12.41 24.374,12.41 24.55,12.586 24.55,12.936 24.814,13.2 25.186,13.2 25.976,12.41 30.307,12.41 30.347,12.45 36.436,12.45 36.576,12.31 39.67,12.31 42.71,9.27 43.384,9.27 43.564,9.45 43.936,9.45 44.116,9.27 49.906,9.27 50.136,9.5 51.614,9.5 51.924,9.19 54.197,9.19 54.757,9.75 56.5,9.75 56.854,9.396 IC8.3@57.3,9.396 57.3,9.416 57.305,9.421 57.421,9.421 57.481,9.48 57.769,9.48 57.829,9.421 57.945,9.421 IC8.4@57.95,9.416
+V_LINO: C23.2 C24.2 C25.2 R40.1 X11.P90 X11.P92 X11.P94 X11.P96 X11.P98 X11.P100 | length 12
  Top Layer w0.3: R40.1@16.185,7.685 17.253,7.685 17.741,8.173 C23.2@17.816,8.173 C24.2@19.041,8.173 20.197,8.173 C25.2@21.865,6.505 ; X11.P90@23.62,11 X11.P92@23.62,10.6 X11.P94@23.62,10.2 X11.P96@23.62,9.8 X11.P98@23.62,9.4 X11.P100@23.62,9 23.62,8.185 22.14,6.705 22.065,6.705 C25.2@21.865,6.505 ; C25.2@21.865,6.505 C25.2@21.865,6.43 C25.2@21.865,6.505
+V_SODIMM: C16.2 C17.2 C18.2 C22.2 C29.2 IC5.3 IC6.3 R40.4 R43.2 R45.2 TP14.1 X1.251 X1.253 X1.255 X1.257 X1.259 | length 252.9
  Top Layer w0.1: v1(61.75,24) 62.204,24 ; R45.2@62.204,23.752 62.204,24 ; R43.2@62.204,24.252 62.204,24
  Top Layer w0.25: v1(65.5,3.75) 65.925,3.325 X1.251@65.925,1.362 ; v1@66.225,3.75 v1(66.25,3.75) ; v1@66.275,3.775 v1(66.25,3.75) ; X1.253@66.425,1.362 66.425,3.534 66.25,3.709 v1(66.25,3.75) ; X1.255@66.925,1.362 66.925,3.584 67,3.659 v1(67,3.7) 67.029,3.671 67.029,3.271 67.425,2.875 ; X1.257@67.425,1.362 67.425,2.875 ; X1.259@67.925,1.362 67.925,2.375 67.425,2.875
  Top Layer w0.3: IC5.3@14.426,17.573 14.441,17.573 C22.2@14.441,16.385 14.481,16.345 14.481,15.769 v1(14.5,15.75) ; v1(14.5,7.5) 14.481,7.519 13.557,7.519 R40.4@13.391,7.685 13.515,7.685 13.9,8.07 13.966,8.07 14.127,8.231 14.481,8.231 v1(14.5,8.25) ; IC6.3@62.89,20.437 62.89,20.414 C29.2@64.078,20.414 ; v1(65.5,3.75) 64.96,4.29 C18.2@64.96,4.642 C17.2@64.96,5.242 65.355,5.242 C16.2@65.51,5.397 65.62,5.397 65.873,5.65 v1(65.9,5.65) ; v1(66.25,5.35) 66.225,5.35 65.925,5.65 v1(65.9,5.65) ; v1(66.25,6) v1(65.9,5.65) ; C29.2@64.078,20.414 64.223,20.269 64.731,20.269 v1(64.75,20.25) 64.777,20.25 64.956,20.429 65.673,20.429 TP14.1@65.951,20.707 65.677,20.981 64.769,20.981 v1(64.75,21) 64.739,21 64.153,20.414 C29.2@64.078,20.414
  Mid 3 w0.3: v1(65.5,3.75) 65.481,3.769 64.854,3.769 63.7,4.923 63.7,5.664 62.8,6.564 62.8,12.936 63.7,13.836 63.7,15.36 63.35,15.71 63.35,20.036 61.75,21.636 v1(61.75,24) v1(64.75,21) v1(64.75,20.25) 64.769,20.231 64.849,20.231 65.83,19.25 65.83,16.716 65.8,16.686 65.8,14.495 65.95,14.345 65.95,12.153 65.8,12.003 65.8,10.47 64.3,8.97 64.3,7.314 65.6,6.014 66.236,6.014 v1(66.25,6)
  Mid 1 w0.25: v1(61.75,24) 61.75,21.601 63.68,19.671 63.68,13.781 63.575,13.676 63.575,13.324 63.68,13.219 63.68,7.082 65.5,5.262 65.5,5.237 ; v1(64.75,21) v1(64.75,20.25) 64.75,18.601 65.175,18.176 65.175,15.8 65.075,15.7 65.075,11.122 65.175,11.022 65.175,6.445 65.62,6 v1(66.25,6) 66.909,5.341 66.909,4.841 67,4.75 v1(67,3.7) ; v1(65.9,5.65) 65.9,5.637 65.5,5.237 ; v3(65.925,2.125) 65.925,3.325 v1(65.5,3.75) 65.5,5.237 ; v1(66.25,5.35) v1(66.25,3.75) 66.25,3.005 66.425,2.83 v3(66.425,2.125) ; v3(66.925,2.125) 66.925,2.855 67,2.93 ; v3(67.425,2.125) 67.425,2.505 67,2.93 ; v3(67.925,2.125) 67.925,2.775 v1(67,3.7) ; 67,2.93 v1(67,3.7)
  Bottom Layer w0.3: v1(14.5,15.75) v1(14.5,8.25) ; v1(14.5,17.25) 15.39,16.36 15.39,8.81 15.95,8.25 ; v1(65.9,5.65) 65.9,6 ; v1(66.25,6) 65.9,6 ; v1(67,3.7) 66.973,3.7 66.923,3.75 v1(66.25,3.75) v1(65.5,3.75) 64.636,3.75 63.586,4.8 60.064,4.8 59.164,5.7 57.06,5.7 55.626,5.7 55.45,5.876 55.45,6.186 55.186,6.45 54.814,6.45 54.444,6.08 54.444,5.974 54.228,5.758 51.795,5.758 51.026,4.99 49.376,4.99 49.186,4.8 48.586,4.8 47.686,5.7 45.814,5.7 45.664,5.55 44.836,5.55 44.586,5.8 41.414,5.8 41.214,5.6 40.86,5.6 38.51,7.95 28.17,7.95 26.97,9.15 24.255,9.15 22.605,7.5 v1(14.5,7.5) v1(14.5,8.25) ; v1(14.5,8.25) 15.95,8.25 ; 15.95,8.25 20.36,8.25 22.31,10.2 30.92,10.2 31.25,10.53 37.77,10.53 41.25,7.05 42.054,7.05 42.059,7.045 42.431,7.045 42.436,7.05 44.05,7.05 44.2,7.2 47.686,7.2 47.95,6.936 47.95,6.87 49.08,5.74 49.374,5.74 49.564,5.55 49.936,5.55 50.2,5.814 50.2,5.84 50.89,6.53 64.106,6.53 64.636,6 65.9,6
  other v3: 65.925,0.6 66.425,0.6 66.925,0.6 67.425,0.6 67.925,0.6
ADC_1: X1.2 X11.P2 | length 50.3
  Top Layer w0.15: X11.P2@23.62,28.6 24.35,28.6 v1(25,29.25)
  Mid 2 w0.095: v1(2.5,22.5) 2.848,22.848 6.161,22.848 6.856,22.153 8.125,22.153 9.394,22.153 9.598,22.356 9.598,23.048 15.605,29.055 19.083,29.055 19.266,29.238 20.055,29.238 20.123,29.17 24.43,29.17 24.51,29.25 v1(25,29.25)
  Mid 4 w0.09: v2(1.675,2.425) 1.405,2.695 1.405,3.724 4.345,6.664 4.345,8.861 2.36,10.846 2.36,17.016 2.5,17.156 v1(2.5,22.5)
  other v2: 1.675,0.6
ADC_2: X1.4 X11.P4 | length 49.2
  Top Layer w0.15: X11.P4@23.62,28.2 24.699,28.2 v1@24.999,28.5
  Mid 2 w0.095: v1(3.25,22.5) 5.92,22.5 6.52,21.9 9.5,21.9 9.9,22.3 9.9,22.891 15.859,28.85 19.154,28.85 19.347,29.042 19.975,29.042 20.107,28.91 24.59,28.91 v1(25,28.5)
  Mid 4 w0.09: v2(2.175,2.425) 2.175,4.225 4.535,6.585 4.535,8.94 2.55,10.925 2.55,16.937 2.69,17.077 2.69,21.94 v1(3.25,22.5)
  other v2: 2.175,0.6
ADC_3: X1.6 X12.S1 | length 70.1
  Top Layer w0.15: X12.S1@45.98,26.1 46,26.12 v4(46,26.47)
  Mid 4 w0.09: v2(2.675,2.425) 2.675,4.456 4.725,6.506 4.725,9.018 2.74,11.003 2.74,16.859 2.88,16.999 2.88,21.499 3.595,22.214 3.595,23.655 v1(3.25,24)
  Mid 1 w0.09: v1(3.25,24) 3.29,23.96 8.24,23.96 10.74,26.46 19.451,26.46 20.601,27.61 21.652,27.61 21.857,27.405 22.605,27.405 24.1,28.9 38.71,28.9 39.07,28.54 40.22,28.54 41.26,27.5 44.97,27.5 45.43,27.04 v4(46,26.47)
  other v2: 2.675,0.6
ADC_4: X1.8 X12.S3 | length 68.4
  Top Layer w0.15: v4(44.92,26.89) 44.92,26.04 45.26,25.7 X12.S3@45.98,25.7
  Mid 4 w0.09: v2(3.175,2.425) 3.175,3.035 3.655,3.515 3.655,5.167 4.915,6.427 4.915,9.097 2.93,11.082 2.93,16.78 3.07,16.92 3.07,21.42 4,22.35 v1(4,23.25)
  Mid 1 w0.09: v1(4,23.25) 7.77,23.25 8.115,23.595 9.095,23.595 11.68,26.18 19.56,26.18 20.75,27.37 21.61,27.37 21.765,27.215 22.825,27.215 23.705,28.095 39.988,28.095 40.143,28.095 41.078,27.16 44.65,27.16 v4(44.92,26.89)
  other v2: 3.175,0.6
CAN_1_RX: X1.22 X11.P12 | length 43.1
  Top Layer w0.15: X11.P12@23.62,26.6 24.389,26.6 24.625,26.836 24.625,27.155 24.845,27.375 25.375,27.375 v1(25.75,27.75)
  Mid 2 w0.095: v1(7,19.5) 9.78,19.5 15.39,25.11 17.56,25.11 19.85,27.4 25.4,27.4 v1(25.75,27.75)
  Mid 4 w0.09: v2(6.675,2.425) 6.655,2.445 6.655,4.775 8.1,6.22 8.1,16.23 7.38,16.95 7.38,19.12 v1(7,19.5)
  other v2: 6.675,0.6
CAN_1_TX: X1.20 X11.P10 | length 45.6
  Top Layer w0.15: X11.P10@23.62,27 23.641,27.021 24.287,27.021 24.375,27.109 24.375,27.425 24.699,27.749 v1(25,27.75)
  Mid 2 w0.095: v1(4.75,21) 10.22,21 15.24,26.02 17.529,26.02 19.606,28.098 24.653,28.098 v1(25,27.75)
  Mid 4 w0.09: v1(4.75,21) 5.155,20.595 5.155,17.615 7.37,15.4 7.37,6.08 6.33,5.04 6.33,4.33 5.905,3.905 5.905,2.695 v2(6.175,2.425)
  other v2: 6.175,0.6
CAN_2_RX: X1.26 X12.S30 | length 66.4
  Top Layer w0.15: X12.S30@48.62,20.5 49.95,20.5 v1(50.5,21.05)
  Mid 3 w0.095: v1(45.25,4.5) 45.25,4.009 45.856,3.402 46.603,3.402 47.848,4.647 47.848,17.778 49.34,19.27 49.34,20.22 49.61,20.49 49.94,20.49 v1(50.5,21.05)
  Mid 1 w0.09: v1(7.75,4.5) 8.1,4.15 35.84,4.15 36.93,5.24 39.58,5.24 40.23,5.89 44.348,5.89 45.25,4.988 v1(45.25,4.5)
  Bottom Layer w0.15: X1.26@7.675,1.362 7.575,1.462 7.575,2.645 7.375,2.845 7.375,3.155 7.595,3.375 7.655,3.375 7.875,3.595 7.875,3.951 7.751,4.075 7.751,4.499 v1(7.75,4.5)
  other v2: 7.675,0.6
CAN_2_TX: X1.24 X12.S28 | length 63.7
  Top Layer w0.15: X12.S28@48.62,20.9 49.532,20.9 49.682,21.05 v1(49.75,21.05)
  Mid 3 w0.095: v1(47.5,5.25) 47.5,6.259 47.07,6.689 47.07,17.56 48.75,19.24 48.75,20.05 v1(49.75,21.05)
  Mid 1 w0.09: v1(7.75,5.25) 8.1,4.9 35.37,4.9 36.125,5.655 38.685,5.655 39.2,6.17 44.53,6.17 45.045,5.655 47.095,5.655 v1(47.5,5.25)
  Bottom Layer w0.15: X1.24@7.175,1.362 7.175,2.691 6.625,3.241 6.625,3.595 6.625,4.125 v1(7.75,5.25)
  other v2: 7.175,0.6
CSI_1_CLK_N: X1.113 X12.S78 | length 30
  Top Layer w0.075: X1.113@29.425,1.362 29.293,1.494 29.293,2.731 29.369,2.806 29.369,4.294 29.5,4.425 v1(29.5,4.5)
  Mid 3 w0.08: v1(29.5,4.5) 29.5,4.587 29.395,4.692 29.395,7.746 29.133,8.008 29.133,10.15 29.183,10.2 29.403,10.2 29.45,10.247 29.45,10.363 29.403,10.41 29.2,10.41 29.133,10.477 29.133,10.808 29.18,10.855 29.308,10.855 29.413,10.75 v1(29.5,10.75)
  Mid 1 w0.08: v1(29.5,10.75) 29.587,10.75 29.673,10.836 29.773,10.836 29.989,10.62 41.73,10.62 41.955,10.845 42.386,10.845 42.551,10.68 43.449,10.68 43.609,10.84 44.019,10.84 44.239,10.62 47.761,10.62 47.87,10.73 47.934,10.73 47.98,10.776 47.98,10.84 48.037,10.896 48.216,10.896 v3(48.22,10.9)
  other v3: 29.425,0.6
CSI_1_CLK_P: X1.111 X12.S76 | length 30
  Top Layer w0.075: X1.111@28.925,1.362 29.056,1.494 29.056,2.829 29.131,2.904 29.131,4.294 29,4.425 v1(29,4.5)
  Mid 3 w0.08: v1(29,4.5) 29,4.587 29.105,4.692 29.105,7.626 28.843,7.888 28.843,10.928 29.06,11.145 29.308,11.145 29.413,11.25 v1(29.5,11.25)
  Mid 1 w0.08: v1(29.5,11.25) 29.587,11.25 29.711,11.126 29.893,11.126 30.109,10.91 41.61,10.91 41.835,11.135 42.506,11.135 42.671,10.97 43.329,10.97 43.489,11.13 44.139,11.13 44.359,10.91 47.641,10.91 47.917,11.186 48.06,11.186 48.174,11.3 v3(48.22,11.3)
  other v3: 28.925,0.6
